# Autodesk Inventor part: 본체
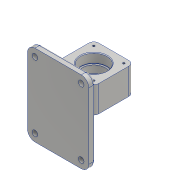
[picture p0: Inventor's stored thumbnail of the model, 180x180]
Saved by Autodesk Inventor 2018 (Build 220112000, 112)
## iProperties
Created: 2020-11
Part Number: 본체
Material: 알루미늄 6061
Document SubType Name: Modeling
Designer: Administrator
Density: 2.7 g/cm^3
Appearance: 알루미늄 - 평지
Mass: 683.214 g
Surface Area: 542.794 cm^2
Volume: 253.042 cm^3
Author: Administrator
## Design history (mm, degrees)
sketch "스케치1"
  geometry: L1 (32, -32)-(-32, -32); L2 (-32, -32)-(-32, 32); L3 (-32, 32)-(32, 32); L4 (32, 32)-(32, -32); L5 (32, -32)-(-32, 32); L6 (-32, -32)-(32, 32); 1 further point
  constraints: 12 end point, 2 midpoint, 2 parallel, 1 horizontal, 1 perpendicular
  dimensions: "d0" = 64 distance of L2.end L3.end; "d1" = 64 distance of L1.end L2.end
extrude "돌출1" new body sketch "스케치1" distance "d2" = 42; taper "d3" = 0 deg
sketch "스케치2"
  geometry: L1 (0, -8.4)-(0, 50.4) reference; L2 (0, 0)-(-21, 0); L3 (-21, 0)-(-21, 15); L4 (-21, 15)-(0, 15); L5 (0, 15)-(0, 0); L6 (0, 15)-(-18, 15); L7 (-18, 15)-(-18, 27); L8 (-18, 27)-(0, 27); L9 (0, 27)-(0, 15); L10 (32, 42)-(-32, 42) reference; L11 (0, 27)-(-21, 27); L12 (-21, 27)-(-21, 42); L13 (-21, 42)-(0, 42); L14 (0, 42)-(0, 27)
  constraints: 24 end point, 6 parallel, 3 horizontal, 3 perpendicular, 2 point on line
  dimensions: "d4" = 15 distance between parallel lines of L4 L2; "d5" = 15 distance between parallel lines of L10 L8; "d6" = 42 diameter of L3 L1; "d7" = 36 diameter of L7 L1
revolve "회전1" sketch "스케치2" stored, may be unused: angle "d8" = 90 deg
fillet "모깎기1" dims "d9" = 0.3
chamfer "모따기1" distance "d10" = 1; stored, may be unused: second distance "d11" = 2, angle "d12" = 45 deg
node "작업 평면1"
sketch "스케치3"
  geometry: L1 (0, 0)-(0, 21); L2 (0, 21)-(-62, 21); L3 (-62, 21)-(-62, 86); L4 (-62, 86)-(36, 86); L5 (36, 86)-(36, -44); L6 (36, -44)-(-62, -44); L7 (-62, -44)-(-62, 21)
  constraints: 14 end point, 3 perpendicular, 1 horizontal, 1 point on line, 1 vertical
  dimensions: "d14" = 21 distance of L1.start L1.end; "d15" = 62 distance of L1.end L2.end; "d16" = 65 distance of L2.end L3.end; "d17" = 98 distance of L3.end L4.end; "d18" = 130 distance of L4.end L5.end; "d19" = 98 distance of L5.end L6.end
extrude "돌출2" join sketch "스케치3" distance "d20" = 10; taper "d21" = 0 deg
sketch "스케치4"
  geometry: L1 (0, -21)-(0, 0); L2 (-20, -25)-(20, -25); L3 (20, -25)-(20, -17); L4 (20, -17)-(-20, -17); L5 (-20, -17)-(-20, -25); L6 (-20, -25)-(20, -17); L7 (20, -25)-(-20, -17); L8 (-4, -38)-(4, -38); L9 (4, -38)-(4, -4); L10 (4, -4)-(-4, -4); L11 (-4, -4)-(-4, -38); L12 (-4, -38)-(4, -4); L13 (4, -38)-(-4, -4)
  constraints: 26 end point, 4 midpoint, 4 parallel, 2 horizontal, 2 perpendicular, 1 vertical
  dimensions: "d22" = 21 distance of L1.start L1.end; "d23" = 8 distance between parallel lines of L11 L9; "d24" = 8 distance between parallel lines of L2 L4; "d25" = 34 distance of L10.end L8.start; "d26" = 40 distance of L2.start L2.end
extrude "돌출3" join sketch "스케치4" stored distance "d27" = 10; taper "d28" = 0 deg
fillet "모깎기2" dims "d29" = 3
fillet "모깎기3" dims "d30" = 12
fillet "모깎기4" dims "d31" = 3
fillet "모깎기5" dims "d32" = 8
sketch "스케치5"
  geometry: L1 (24, -24)-(-24, -24); L2 (-24, -24)-(-24, 24); L3 (-24, 24)-(24, 24); L4 (24, 24)-(24, -24); L5 (24, -24)-(-24, 24); L6 (-24, -24)-(24, 24); 5 further points
  constraints: 12 end point, 4 coincident, 2 midpoint, 2 parallel, 1 horizontal, 1 perpendicular
  dimensions: "d33" = 48 distance of L2.end L3.end; "d34" = 48 distance of L1.end L2.end
hole "구멍1" sketch "스케치5" at (-24, 24), (24, 24), (24, -24), (-24, -24) diameter "d35" = 3.242; stored, may be unused: countersink angle "d39" = 90 deg, drill point angle "d41" = 118 deg; dims "d36" = 8, "d37" = 4, "d38" = 2, "d40" = 10
sketch "스케치6"
  geometry: L1 (24, -24)-(-24, -24); L2 (-24, -24)-(-24, 24); L3 (-24, 24)-(24, 24); L4 (24, 24)-(24, -24); L5 (24, -24)-(-24, 24); L6 (-24, -24)-(24, 24); C1 r 1.621 at (24, 24) reference; C2 r 1.621 at (24, -24) reference; C3 r 1.621 at (-24, -24) reference; 5 further points
  constraints: 12 end point, 4 coincident, 2 midpoint, 2 parallel, 1 horizontal, 1 perpendicular
  dimensions: "d42" = 48 distance of L2.end L3.end; "d43" = 48 distance of L1.end L2.end
hole "구멍2" sketch "스케치6" at (-24, 24), (24, 24), (24, -24), (-24, -24) diameter "d44" = 3.242; stored, may be unused: countersink angle "d48" = 90 deg, drill point angle "d50" = 118 deg; dims "d45" = 8, "d46" = 4, "d47" = 2, "d49" = 10
sketch "스케치7"
  geometry: C1 r 4.5 at (-24, -74); C2 r 4.5 at (-24, 32); C3 r 4.5 at (50, -74); C4 r 4.5 at (50, 32); A1 r 12 centre (-24, -74) between (-36, -74) and (-24, -86) reference; A2 r 12 centre (-24, 32) between (-24, 44) and (-36, 32) reference; A3 r 12 centre (50, -74) between (50, -86) and (62, -74) reference; A4 r 12 centre (50, 32) between (62, 32) and (50, 44) reference; 1 further point
  constraints: 4 centre point, 4 coincident
  dimensions: "d51" = 9 diameter of C1; "d52" = 9 diameter of C2; "d53" = 9 diameter of C3; "d54" = 9 diameter of C4
extrude "돌출4" cut sketch "스케치7" distance "d55" = 10; taper "d56" = 0 deg
sketch "스케치8"
  geometry: L1 (62, -74)-(62, 32) reference; L2 (-24, -86)-(50, -86) reference; 2 further points
  constraints: 1 other
  dimensions: "d57" = 10 distance from line of L1 point (52, -21); "d58" = 65 distance from line of L2 point (52, -21)
feature "엠보싱1" sketch "스케치8" dims "d0" = 64, "d1" = 64, "d59" = 0.5, "d60" = 0
node "솔리드1"
